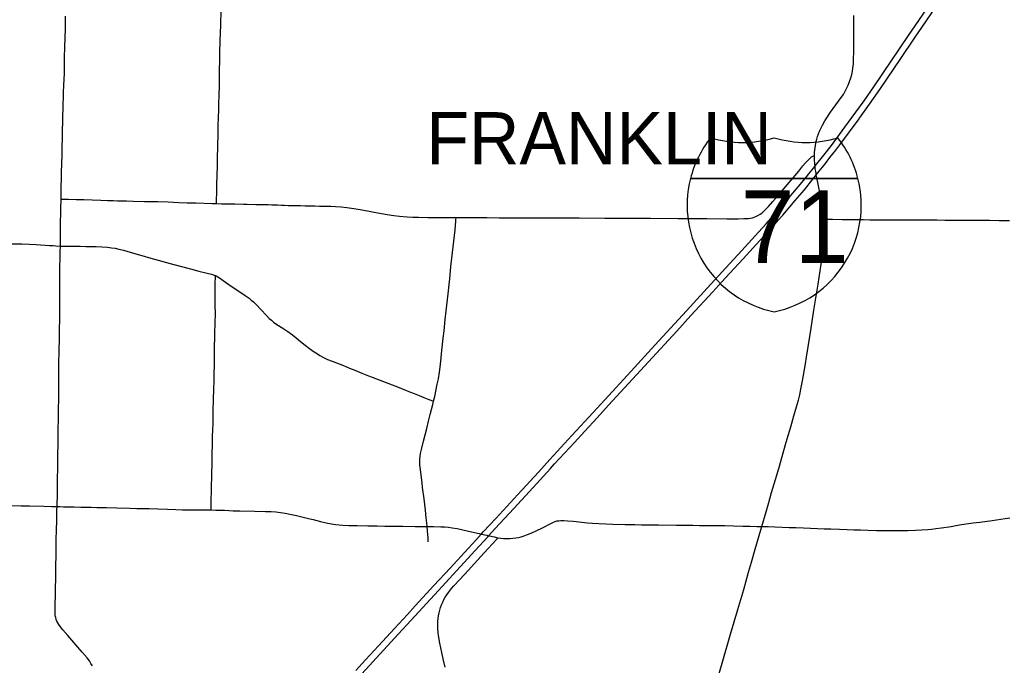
# Model space of a CAD drawing. Extents: x 9078 to 9739, y 4248 to 4966.
# Drawn here: x 9545.7 to 9630.7, y 4579 to 4634.7 of the extents above; entities that cross this region are included whole.
import ezdxf

# ---------------------------------------------------------------- set-up
doc = ezdxf.new("R2010")
doc.units = 0
for name, color, linetype in [('GM_X_County_Road', 7, 'Continuous'), ('GM_X_Interstate_Route', 7, 'Continuous'), ('GM_X_Interstate_Shield', 7, 'Continuous'), ('GM_X_State_Route', 7, 'Continuous'), ('GM_X_Township_Road', 7, 'Continuous'), ('GM_X_Township_Text', 7, 'Continuous')]:
    doc.layers.add(name, color=color, linetype=linetype)

msp = doc.modelspace()

# ---------------------------------------------------------------- linework, layer by layer
at = {"layer": 'GM_X_County_Road'}
for points in [[(9549.258, 4619.194), (9549.263, 4619.718), (9549.303, 4621.522), (9549.343, 4622.997), (9549.358, 4623.571), (9549.38, 4624.553), (9549.421, 4626.439), (9549.433, 4626.931), (9549.477, 4628.406), (9549.498, 4628.98), (9549.54, 4630.045), (9549.565, 4631.274), (9549.587, 4632.422), (9549.606, 4632.994), (9549.627, 4633.977), (9549.648, 4634.959)], [(9549.196, 4615.157), (9549.205, 4615.635), (9549.211, 4616.441), (9549.222, 4617.261), (9549.23, 4617.916), (9549.242, 4618.49), (9549.257, 4619.144), (9549.258, 4619.194)], [(9535.868, 4615.753), (9536.712, 4615.649), (9537.364, 4615.572), (9538.913, 4615.397), (9539.728, 4615.307), (9540.138, 4615.272), (9540.466, 4615.264), (9541.123, 4615.272), (9542.846, 4615.316), (9543.83, 4615.335), (9544.404, 4615.341), (9545.306, 4615.342), (9545.879, 4615.333), (9546.534, 4615.308), (9547.107, 4615.276), (9548.253, 4615.202), (9548.577, 4615.19), (9548.82, 4615.174), (9549.142, 4615.159), (9549.196, 4615.157)], [(9548.913, 4592.716), (9548.919, 4592.891), (9548.939, 4593.709), (9548.952, 4594.61), (9548.979, 4596.495), (9548.985, 4596.987), (9548.995, 4598.299), (9549.009, 4599.118), (9549.028, 4600.429), (9549.038, 4601.085), (9549.057, 4601.987), (9549.067, 4602.889), (9549.067, 4603.626), (9549.07, 4604.199), (9549.073, 4604.938), (9549.088, 4606.167), (9549.11, 4607.151), (9549.128, 4607.806), (9549.144, 4609.037), (9549.15, 4609.693), (9549.15, 4610.43), (9549.15, 4611.085), (9549.15, 4611.656), (9549.166, 4612.803), (9549.188, 4614.683), (9549.196, 4615.157)], [(9549.196, 4615.157), (9549.223, 4615.155), (9549.3, 4615.156), (9550.164, 4615.144), (9550.409, 4615.142), (9550.9, 4615.137), (9551.391, 4615.121), (9551.799, 4615.118), (9552.29, 4615.106), (9552.781, 4615.085), (9553.271, 4615.049), (9553.596, 4615.012), (9553.918, 4614.962), (9554.238, 4614.896), (9554.634, 4614.793), (9555.5, 4614.542), (9556.209, 4614.336), (9556.997, 4614.11), (9557.628, 4613.932), (9558.336, 4613.73), (9558.968, 4613.552), (9560.397, 4613.181), (9561.115, 4613.005), (9561.832, 4612.832), (9562.226, 4612.724), (9562.458, 4612.647), (9562.557, 4612.606)], [(9562.557, 4612.606), (9562.608, 4612.585), (9562.753, 4612.512), (9562.892, 4612.429), (9563.231, 4612.2), (9563.83, 4611.768), (9564.301, 4611.439), (9565.117, 4610.888), (9565.452, 4610.654), (9565.644, 4610.503), (9565.827, 4610.341), (9566.118, 4610.054), (9566.458, 4609.699), (9566.961, 4609.158), (9567.193, 4608.924), (9567.375, 4608.758), (9567.568, 4608.602), (9567.77, 4608.459), (9568.459, 4608.014), (9568.797, 4607.783), (9569.193, 4607.492), (9569.515, 4607.24), (9569.895, 4606.929), (9570.279, 4606.623), (9570.672, 4606.326), (9571.073, 4606.04), (9571.346, 4605.856), (9571.558, 4605.73), (9571.922, 4605.538), (9572.219, 4605.395), (9572.599, 4605.238), (9573.211, 4605), (9573.592, 4604.85), (9574.113, 4604.636), (9574.562, 4604.453), (9575.165, 4604.208), (9575.744, 4603.975), (9576.058, 4603.856), (9576.807, 4603.577), (9577.784, 4603.198), (9578.233, 4603.028), (9578.914, 4602.75), (9579.369, 4602.566), (9579.672, 4602.445), (9580.118, 4602.267), (9580.496, 4602.116), (9580.95, 4601.932), (9581.345, 4601.784)], [(9580.803, 4590.984), (9580.774, 4591.277), (9580.72, 4591.751), (9580.641, 4592.402), (9580.525, 4593.379), (9580.4, 4594.354), (9580.35, 4594.761), (9580.272, 4595.411), (9580.214, 4595.9), (9580.176, 4596.309), (9580.165, 4596.556), (9580.169, 4596.803), (9580.193, 4597.05), (9580.233, 4597.294), (9580.303, 4597.615), (9580.483, 4598.331), (9580.764, 4599.443), (9580.919, 4600.079), (9581.056, 4600.635), (9581.276, 4601.506), (9581.345, 4601.784)], [(9551.954, 4578.991), (9551.832, 4579.204), (9551.694, 4579.408), (9551.495, 4579.668), (9551.079, 4580.175), (9550.704, 4580.611), (9549.838, 4581.596), (9549.408, 4582.092), (9549.203, 4582.348), (9549.065, 4582.552), (9548.982, 4582.693), (9548.907, 4582.839), (9548.843, 4582.99), (9548.795, 4583.147), (9548.763, 4583.307), (9548.746, 4583.471), (9548.739, 4583.717), (9548.753, 4584.455), (9548.767, 4584.946), (9548.783, 4585.519), (9548.791, 4585.928), (9548.793, 4586.255), (9548.795, 4587.075), (9548.814, 4587.813), (9548.824, 4588.305), (9548.848, 4589.781), (9548.866, 4590.765), (9548.885, 4591.42), (9548.895, 4591.83), (9548.905, 4592.401), (9548.913, 4592.716)], [(9591.436, 4591.259), (9591.445, 4591.264), (9591.665, 4591.364), (9591.815, 4591.424), (9591.975, 4591.469), (9592.139, 4591.494), (9592.304, 4591.509), (9592.574, 4591.509), (9592.88, 4591.488), (9593.37, 4591.445), (9594.617, 4591.314), (9595.031, 4591.274), (9595.57, 4591.25), (9596.799, 4591.204), (9597.85, 4591.174), (9598.67, 4591.156), (9599.244, 4591.144), (9599.653, 4591.141), (9600.062, 4591.138), (9600.308, 4591.136), (9600.636, 4591.133), (9600.718, 4591.132), (9602.275, 4591.113), (9603.423, 4591.101), (9603.505, 4591.1), (9603.682, 4591.1), (9604.245, 4591.088), (9604.962, 4591.084), (9605.596, 4591.085), (9606.004, 4591.08)], [(9609.619, 4590.99), (9609.731, 4590.991), (9610.181, 4590.981), (9610.743, 4590.963), (9611.972, 4590.914), (9612.546, 4590.895), (9613.202, 4590.871), (9614.43, 4590.821), (9615, 4590.797), (9615.573, 4590.779), (9616.309, 4590.753), (9616.964, 4590.73), (9617.538, 4590.713), (9618.111, 4590.7), (9618.766, 4590.68), (9619.503, 4590.66), (9620.405, 4590.642), (9620.978, 4590.636), (9621.716, 4590.649), (9622.207, 4590.661), (9622.862, 4590.676), (9623.381, 4590.704), (9623.926, 4590.739), (9624.225, 4590.766), (9624.607, 4590.81), (9625.094, 4590.877), (9625.93, 4591.007), (9626.319, 4591.067), (9626.834, 4591.152), (9627.418, 4591.242), (9627.839, 4591.306), (9628.399, 4591.376), (9629.454, 4591.519), (9630.589, 4591.67), (9630.99, 4591.728)], [(9580.803, 4590.984), (9581.332, 4590.98), (9581.978, 4590.972), (9582.305, 4590.961), (9582.633, 4590.932), (9582.96, 4590.888), (9583.364, 4590.815), (9584.245, 4590.619), (9585.123, 4590.414), (9585.278, 4590.38)], [(9586.901, 4590.025), (9587.125, 4589.993), (9587.368, 4589.971), (9587.613, 4589.963), (9587.939, 4589.967), (9588.183, 4589.983), (9588.426, 4590.013), (9588.666, 4590.056), (9588.904, 4590.111), (9589.139, 4590.179), (9589.446, 4590.29), (9589.823, 4590.448), (9590.194, 4590.62), (9590.781, 4590.912), (9591.436, 4591.259)], [(9606.004, 4591.08), (9606.427, 4591.074), (9607.179, 4591.051), (9607.983, 4591.028), (9608.381, 4591.019), (9608.618, 4591.011), (9609.188, 4590.995), (9609.433, 4590.99), (9609.619, 4590.99)], [(9585.278, 4590.38), (9585.349, 4590.364), (9585.457, 4590.34), (9585.923, 4590.234), (9586.09, 4590.194), (9586.173, 4590.175), (9586.563, 4590.091), (9586.883, 4590.028), (9586.901, 4590.025)]]:
    msp.add_lwpolyline(points, dxfattribs=at)
at = {"layer": 'GM_X_Interstate_Route'}
for points in [[(9618.011, 4626.12), (9618.048, 4626.17), (9618.902, 4627.374), (9619.79, 4628.653), (9621.583, 4631.301), (9622.781, 4633.065), (9625.59, 4637.203), (9626.12, 4637.984), (9626.419, 4638.425), (9627.154, 4639.512), (9627.891, 4640.598), (9629.09, 4642.362), (9630.151, 4643.922), (9630.6, 4644.584), (9631.026, 4645.211)], [(9574.662, 4578.59), (9575.494, 4579.497), (9576.599, 4580.709), (9577.989, 4582.217), (9579.101, 4583.424), (9579.764, 4584.152), (9581.372, 4585.905), (9582.761, 4587.414), (9584.985, 4589.827), (9585.457, 4590.34), (9585.497, 4590.384), (9585.629, 4590.527), (9586.71, 4591.696), (9588.597, 4593.75), (9590.374, 4595.683), (9591.372, 4596.771), (9593.255, 4598.829), (9594.366, 4600.036), (9596.089, 4601.906), (9598.362, 4604.384), (9600.417, 4606.616), (9603.13, 4609.581), (9604.63, 4611.21), (9606.183, 4612.902), (9607.903, 4614.777), (9609.346, 4616.347), (9610.007, 4617.078), (9611.041, 4618.245), (9611.947, 4619.305), (9612.947, 4620.5), (9613.472, 4621.131), (9613.678, 4621.386), (9613.95, 4621.721), (9614.04, 4621.832), (9614.202, 4622.038), (9614.242, 4622.09), (9614.959, 4622.987), (9615.611, 4623.831), (9616.548, 4625.077), (9617.327, 4626.133), (9618.424, 4627.668), (9619.268, 4628.879), (9622.257, 4633.293), (9623.133, 4634.582), (9624.514, 4636.618)], [(9611.048, 4617.4), (9611.426, 4617.829), (9612.496, 4619.071), (9613.288, 4620.012), (9614.018, 4620.904), (9614.067, 4620.964), (9614.315, 4621.284), (9614.573, 4621.609), (9614.836, 4621.95), (9615.092, 4622.266), (9615.477, 4622.773), (9615.987, 4623.412), (9616.336, 4623.868), (9617.173, 4624.982), (9618.011, 4626.12)], [(9591.775, 4596.386), (9593.475, 4598.239), (9594.366, 4599.203), (9595.423, 4600.347), (9596.422, 4601.434), (9597.804, 4602.948), (9600.19, 4605.544), (9601.578, 4607.052), (9602.301, 4607.835), (9603.517, 4609.168), (9605.406, 4611.219), (9606.183, 4612.065), (9606.846, 4612.792), (9608.012, 4614.06), (9609.45, 4615.635), (9610.612, 4616.907), (9611.048, 4617.4)], [(9584.577, 4588.549), (9584.931, 4588.934), (9586.01, 4590.106), (9586.09, 4590.194), (9586.652, 4590.807), (9588.266, 4592.554), (9589.931, 4594.366), (9591.423, 4596.003), (9591.775, 4596.386)], [(9559.93, 4561.899), (9560.124, 4562.085), (9560.755, 4562.711), (9561.617, 4563.577), (9562.239, 4564.23), (9565.845, 4568.155), (9567.621, 4570.087), (9570.005, 4572.685), (9571.172, 4573.952), (9572.339, 4575.219), (9573.945, 4576.975), (9575.5, 4578.665), (9576.72, 4579.994), (9578.326, 4581.748), (9579.382, 4582.895), (9581.767, 4585.493), (9584.577, 4588.549)]]:
    msp.add_lwpolyline(points, dxfattribs=at)
at = {"layer": 'GM_X_Interstate_Shield'}
for p, q in [((9603.475, 4620.973), (9617.903, 4620.973)), ((9617.903, 4620.973), (9603.475, 4620.973)), ((9617.903, 4620.973), (9603.475, 4620.973))]:
    msp.add_line(p, q, dxfattribs=at)
for centre, start, end in [((9612.564, 4618.674), 141.66896, 165.80665), ((9607.95, 4633.454), 253.00908, 286.99093), ((9613.429, 4633.454), 253.00908, 286.99093), ((9608.814, 4618.674), 14.19335, 38.33104), ((9612.564, 4618.674), 165.80665, 258.46304), ((9608.814, 4618.674), 281.53696, 14.19335)]:
    msp.add_arc(centre, 9.375, start, end, dxfattribs=at)
at = {"layer": 'GM_X_State_Route'}
for points in [[(9617.542, 4632.347), (9617.543, 4632.466), (9617.541, 4632.958), (9617.536, 4633.696), (9617.535, 4635.007)], [(9614.818, 4614.093), (9614.914, 4614.717), (9615.049, 4615.608), (9615.085, 4615.933), (9615.105, 4616.259), (9615.11, 4616.586), (9615.098, 4616.912), (9615.069, 4617.238), (9615.038, 4617.473), (9615.015, 4617.643), (9614.875, 4618.45), (9614.702, 4619.335), (9614.439, 4620.621), (9614.315, 4621.284), (9614.288, 4621.427), (9614.225, 4621.833), (9614.202, 4622.038), (9614.179, 4622.242), (9614.158, 4622.57), (9614.155, 4622.817), (9614.16, 4622.967), (9614.167, 4623.146), (9614.195, 4623.474), (9614.238, 4623.8), (9614.282, 4624.043), (9614.358, 4624.363), (9614.426, 4624.6), (9614.506, 4624.834), (9614.596, 4625.064), (9614.698, 4625.289), (9614.847, 4625.582), (9615.05, 4625.939), (9615.268, 4626.287), (9615.548, 4626.692), (9616.465, 4627.951), (9616.643, 4628.224), (9616.807, 4628.507), (9616.956, 4628.797), (9617.056, 4629.02), (9617.174, 4629.324), (9617.276, 4629.635), (9617.365, 4629.949), (9617.418, 4630.187), (9617.472, 4630.508), (9617.508, 4630.832), (9617.525, 4631.158), (9617.54, 4631.975), (9617.542, 4632.347)], [(9605.936, 4578.329), (9606.252, 4579.433), (9606.916, 4581.717), (9607.547, 4583.839), (9607.801, 4584.705), (9608.06, 4585.568), (9608.484, 4587.067), (9608.736, 4587.933), (9609.051, 4589.037), (9609.397, 4590.218), (9609.619, 4590.99), (9609.986, 4592.266), (9610.216, 4593.053), (9610.465, 4593.919), (9610.904, 4595.412), (9611.133, 4596.198), (9611.314, 4596.829), (9611.721, 4598.248), (9612.111, 4599.586), (9612.384, 4600.531), (9612.613, 4601.317), (9612.768, 4601.868), (9612.884, 4602.344), (9612.985, 4602.824), (9613.116, 4603.549), (9613.284, 4604.518), (9613.369, 4605.002), (9613.458, 4605.569), (9613.6, 4606.46), (9613.747, 4607.349), (9613.859, 4608.079), (9614.098, 4609.618), (9614.46, 4611.884), (9614.74, 4613.582), (9614.818, 4614.093)]]:
    msp.add_lwpolyline(points, dxfattribs=at)
at = {"layer": 'GM_X_Township_Road'}
for points in [[(9562.652, 4618.814), (9562.659, 4619.083), (9562.677, 4619.82), (9562.688, 4620.477), (9562.732, 4622.035), (9562.742, 4622.691), (9562.755, 4623.758), (9562.78, 4624.825), (9562.8, 4625.482), (9562.818, 4626.302), (9562.834, 4626.794), (9562.845, 4627.369), (9562.864, 4628.189), (9562.891, 4628.961), (9562.899, 4629.584), (9562.902, 4629.913), (9562.913, 4630.486), (9562.923, 4630.979), (9562.945, 4631.799), (9562.971, 4632.867), (9563.008, 4634.18), (9563.036, 4635.493)], [(9608.614, 4617.553), (9608.648, 4617.557), (9608.808, 4617.591), (9608.965, 4617.639), (9609.117, 4617.7), (9609.263, 4617.774), (9609.473, 4617.902), (9609.607, 4617.996), (9609.735, 4618.099), (9609.914, 4618.267), (9610.197, 4618.563), (9610.581, 4618.99), (9611.007, 4619.488), (9611.483, 4620.052), (9612.804, 4621.618), (9613.162, 4622.067), (9613.378, 4622.313), (9613.715, 4622.673), (9613.832, 4622.786), (9613.896, 4622.837), (9613.97, 4622.873), (9614.16, 4622.967)], [(9549.258, 4619.194), (9549.568, 4619.196), (9549.896, 4619.199), (9550.551, 4619.179), (9551.206, 4619.155), (9551.943, 4619.126), (9552.681, 4619.107), (9553.254, 4619.09), (9553.745, 4619.075), (9554.155, 4619.059), (9554.563, 4619.047), (9554.891, 4619.042), (9555.464, 4619.029), (9556.447, 4619.005), (9556.693, 4619), (9557.349, 4618.987), (9557.595, 4618.982), (9558.495, 4618.954), (9559.396, 4618.918), (9560.132, 4618.887), (9560.869, 4618.866), (9562.262, 4618.824), (9562.652, 4618.814)], [(9562.652, 4618.814), (9562.672, 4618.814), (9563.081, 4618.804), (9563.737, 4618.792), (9564.228, 4618.783), (9564.965, 4618.773), (9565.292, 4618.765), (9566.03, 4618.747), (9566.439, 4618.738), (9567.095, 4618.722), (9567.422, 4618.715), (9567.912, 4618.699), (9568.239, 4618.686), (9568.484, 4618.675), (9568.811, 4618.662), (9569.384, 4618.646), (9569.876, 4618.635), (9570.286, 4618.627), (9570.613, 4618.619), (9571.103, 4618.609), (9571.511, 4618.603), (9571.838, 4618.599), (9572.084, 4618.595), (9572.493, 4618.582), (9572.902, 4618.561), (9573.393, 4618.528), (9573.882, 4618.483), (9574.288, 4618.429), (9574.854, 4618.335), (9575.659, 4618.177), (9576.221, 4618.063), (9576.543, 4618.005), (9577.35, 4617.867), (9577.918, 4617.785), (9578.407, 4617.731), (9579.061, 4617.675), (9579.552, 4617.646), (9580.043, 4617.633), (9580.863, 4617.625), (9581.847, 4617.615), (9582.585, 4617.613), (9583.293, 4617.606)], [(9581.345, 4601.784), (9581.455, 4602.2), (9581.667, 4603.242), (9581.762, 4603.723), (9581.852, 4604.288), (9581.935, 4604.937), (9582.069, 4606.156), (9582.179, 4607.212), (9582.246, 4607.863), (9582.356, 4608.837), (9582.434, 4609.569), (9582.6, 4611.032), (9582.688, 4611.845), (9582.736, 4612.334), (9582.845, 4613.392), (9582.979, 4614.611), (9583.034, 4615.099), (9583.086, 4615.588), (9583.192, 4616.563), (9583.269, 4617.296), (9583.275, 4617.378), (9583.293, 4617.606)], [(9583.293, 4617.606), (9583.65, 4617.602), (9584.223, 4617.601), (9584.96, 4617.603), (9585.452, 4617.605), (9585.944, 4617.606), (9587.008, 4617.599), (9587.5, 4617.598), (9588.648, 4617.596), (9590.041, 4617.598), (9590.615, 4617.598), (9591.353, 4617.591), (9591.927, 4617.587), (9592.992, 4617.587), (9593.894, 4617.582), (9596.107, 4617.563), (9597.419, 4617.559), (9598.813, 4617.557), (9600.042, 4617.551), (9602.42, 4617.541), (9603.732, 4617.538), (9604.879, 4617.534), (9606.601, 4617.511), (9607.584, 4617.5), (9608.076, 4617.515), (9608.485, 4617.537), (9608.614, 4617.553)], [(9615.038, 4617.473), (9615.222, 4617.47), (9615.714, 4617.462), (9616.534, 4617.448), (9617.026, 4617.443), (9618.337, 4617.429), (9618.911, 4617.428), (9620.06, 4617.426), (9621.29, 4617.416), (9622.275, 4617.414), (9623.095, 4617.41), (9623.997, 4617.409), (9624.736, 4617.4), (9625.392, 4617.39), (9626.212, 4617.385), (9626.786, 4617.379), (9627.361, 4617.374), (9628.014, 4617.372), (9628.256, 4617.375), (9628.746, 4617.382), (9629.237, 4617.384), (9630.057, 4617.37), (9630.96, 4617.357)], [(9562.176, 4592.418), (9562.179, 4592.545), (9562.18, 4592.625), (9562.185, 4592.881), (9562.191, 4593.147), (9562.197, 4593.487), (9562.204, 4593.837), (9562.213, 4594.259), (9562.217, 4594.468), (9562.221, 4594.665), (9562.232, 4595.074), (9562.246, 4595.647), (9562.262, 4596.301), (9562.268, 4596.791), (9562.272, 4597.119), (9562.298, 4598.181), (9562.309, 4598.587), (9562.338, 4599.482), (9562.347, 4599.728), (9562.355, 4600.055), (9562.364, 4600.626), (9562.369, 4601.035), (9562.386, 4601.853), (9562.425, 4602.917), (9562.442, 4603.49), (9562.449, 4604.062), (9562.463, 4604.961), (9562.47, 4605.453), (9562.485, 4606.271), (9562.512, 4607.499), (9562.541, 4608.646), (9562.548, 4609.219), (9562.544, 4610.119), (9562.536, 4611.51), (9562.536, 4612.002), (9562.55, 4612.411), (9562.557, 4612.606)], [(9544.666, 4592.798), (9545.814, 4592.779), (9546.552, 4592.761), (9547.783, 4592.731), (9548.439, 4592.716), (9548.684, 4592.716), (9548.796, 4592.716), (9548.913, 4592.716)], [(9548.913, 4592.716), (9549.153, 4592.708), (9549.474, 4592.697), (9549.884, 4592.685), (9550.376, 4592.675), (9550.95, 4592.668), (9551.853, 4592.65), (9552.345, 4592.643), (9553.165, 4592.621), (9554.068, 4592.596), (9555.216, 4592.566), (9555.79, 4592.552), (9556.283, 4592.546), (9556.857, 4592.532), (9557.595, 4592.504), (9558.415, 4592.478), (9559.152, 4592.454), (9559.725, 4592.441), (9560.298, 4592.426), (9560.625, 4592.422), (9561.446, 4592.425), (9562.02, 4592.422), (9562.176, 4592.418)], [(9562.176, 4592.418), (9562.594, 4592.407), (9563.332, 4592.387), (9564.07, 4592.349), (9564.644, 4592.337), (9565.956, 4592.32), (9566.857, 4592.293), (9567.348, 4592.28), (9567.756, 4592.255), (9568.163, 4592.21), (9568.569, 4592.15), (9568.971, 4592.07), (9569.53, 4591.938), (9570.566, 4591.684), (9570.966, 4591.592), (9571.603, 4591.434), (9572.081, 4591.32), (9572.563, 4591.219), (9572.887, 4591.167), (9573.212, 4591.127), (9573.54, 4591.1), (9574.032, 4591.081), (9574.77, 4591.065), (9575.672, 4591.055), (9576.493, 4591.044), (9577.149, 4591.035), (9577.888, 4591.025), (9578.708, 4591.012), (9579.773, 4590.996), (9580.431, 4590.984), (9580.803, 4590.984)], [(9580.878, 4589.668), (9580.877, 4589.748), (9580.873, 4589.987), (9580.828, 4590.624), (9580.803, 4590.984)], [(9581.737, 4581.953), (9581.72, 4582.161), (9581.707, 4582.488), (9581.712, 4582.816), (9581.732, 4583.061), (9581.766, 4583.304), (9581.814, 4583.546), (9581.875, 4583.784), (9581.948, 4584.018), (9582.033, 4584.249), (9582.129, 4584.475), (9582.237, 4584.696), (9582.355, 4584.911), (9582.487, 4585.119), (9582.63, 4585.319), (9582.883, 4585.641), (9583.097, 4585.889), (9583.601, 4586.427), (9584.323, 4587.211), (9585.711, 4588.717), (9586.758, 4589.868), (9586.901, 4590.025)], [(9582.337, 4578.863), (9582.18, 4579.583), (9582.059, 4580.143), (9581.898, 4580.946), (9581.779, 4581.591), (9581.746, 4581.834), (9581.737, 4581.953)]]:
    msp.add_lwpolyline(points, dxfattribs=at)

# ---------------------------------------------------------------- texts
at = {"layer": 'GM_X_Interstate_Shield'}
msp.add_text('71', height=6.25, dxfattribs=at).set_placement((9607.802, 4613.707))
at = {"layer": 'GM_X_Township_Text'}
msp.add_text('FRANKLIN', height=4.5, rotation=0.00001, dxfattribs=at).set_placement((9580.718, 4622.191))

doc.saveas('drawing.dxf')
